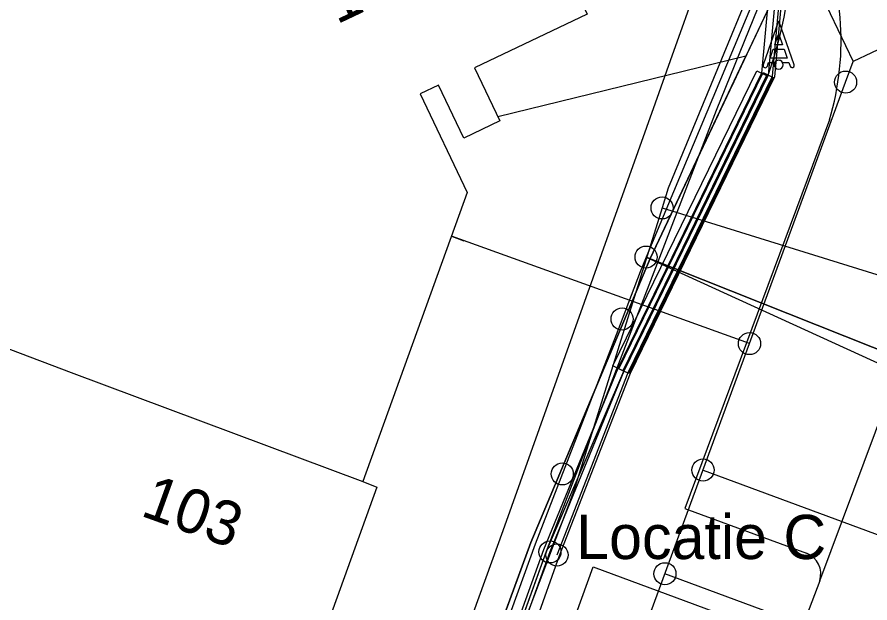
# Model space of a CAD drawing. Extents: x 192672 to 192910, y 446344 to 446512.
# Drawn here: x 192830.88 to 192850.15, y 446438.86 to 446452.12 of the extents above; entities that cross this region are included whole.
import ezdxf

# ---------------------------------------------------------------- set-up
doc = ezdxf.new("R2010")
doc.units = 0
for name, color, linetype in [('B-OI-KL-()_FIREHYDRANT_WATER-S', 7, 'Continuous'), ('B-OI-KL-()_MANTELBUIS_WATER-G', 7, 'Continuous'), ('B-OI-KL-()_PUNTVANLEVERING_WATER-S', 7, 'Continuous'), ('B-OI-KL-BUISLEIDING_OLIEGASCHEMICALIEN_GASLAGEDRUK-G', 7, 'Continuous'), ('B-OI-KL-DATA-G', 7, 'Continuous'), ('B-OI-KL-DATA_GTWP-S', 7, 'Continuous'), ('B-OI-KL-DATA_KABELBED-G', 7, 'Continuous'), ('B-OI-KL-DATA_MANTELBUIS-G', 7, 'Continuous'), ('B-OI-KL-DATA_MOF-S', 7, 'Continuous'), ('B-OI-KL-ET_LS-G', 7, 'Continuous'), ('B-OI-KL-ET_LS_MANTELBUIS-G', 7, 'Continuous'), ('B-OI-KL-ET_LS_MOF-S', 7, 'Continuous'), ('B-OI-KL-ET_MS-G', 7, 'Continuous'), ('B-OI-KL-ET_MS_MANTELBUIS-G', 7, 'Continuous'), ('B-OI-KL-GAS_LD_TSTUK-S', 7, 'Continuous'), ('B-OI-KL-WATER-G', 7, 'Continuous'), ('bovenleidingmast', 7, 'Continuous'), ('Default', 7, 'Continuous'), ('huisnummerreeks BGT', 7, 'Continuous'), ('kant open verharding', 7, 'Continuous'), ('kant verharding', 7, 'Continuous'), ('pand op maaiveld vlak', 7, 'Continuous'), ('TEKST', 7, 'Continuous')]:
    doc.layers.add(name, color=color, linetype=linetype)

# ---------------------------------------------------------------- blocks, each defined once
blk = doc.blocks.new('B-OI-KL-ET_LS_MOF-S')
at = {"layer": 'Default'}
blk.add_circle((0, 0), 0.25, dxfattribs=at)
blk = doc.blocks.new('B-OI-KL-GAS_LD_TSTUK-S')
at = {"layer": 'Default'}
blk.add_circle((0, 0), 0.25, dxfattribs=at)
blk = doc.blocks.new('B-OI-KL-()_FIREHYDRANT_WATER-S')
at = {"layer": 'Default'}
blk.add_circle((0, 0), 0.25, dxfattribs=at)
blk = doc.blocks.new('B-OI-KL-()_PUNTVANLEVERING_WATER-S')
at = {"layer": 'Default'}
blk.add_circle((0, 0), 0.25, dxfattribs=at)
blk = doc.blocks.new('B-OI-KL-DATA_GTWP-S')
at = {"layer": 'Default'}
blk.add_circle((0, 0), 0.25, dxfattribs=at)
blk = doc.blocks.new('B-OI-KL-DATA_MOF-S')
at = {"layer": 'Default'}
blk.add_circle((0, 0), 0.25, dxfattribs=at)

msp = doc.modelspace()

# ---------------------------------------------------------------- linework, layer by layer
at = {"layer": 'B-OI-KL-()_MANTELBUIS_WATER-G'}
msp.add_lwpolyline([(192840.69, 446447.157), (192840.972, 446447.055)], dxfattribs=at)
at = {"layer": 'B-OI-KL-BUISLEIDING_OLIEGASCHEMICALIEN_GASLAGEDRUK-G'}
for points in [[(192822.433, 446509.756), (192825.279, 446503.813), (192831.728, 446490.219), (192841.146, 446471.04), (192848.608, 446455.57), (192845.591, 446448.244), (192845.453, 446447.8)], [(192845.453, 446447.8), (192843.453, 446441.374), (192837.009, 446424.35), (192840.007, 446421.325), (192825.926, 446382.49)], [(192845.453, 446447.8), (192850.863, 446446.116), (192855.911, 446444.404), (192860.643, 446442.932)]]:
    msp.add_lwpolyline(points, dxfattribs=at)
at = {"layer": 'B-OI-KL-DATA-G'}
for points in [[(192821.742, 446509.756), (192825.984, 446501.22), (192835.895, 446480.007), (192842.472, 446466.378), (192848.635, 446454.503), (192848.764, 446454.232), (192845.185, 446446.654), (192842.489, 446440.231), (192836.203, 446423.068)], [(192821.742, 446509.756), (192825.984, 446501.22), (192835.895, 446480.007), (192842.472, 446466.378), (192848.635, 446454.503), (192848.764, 446454.232), (192845.185, 446446.654), (192842.489, 446440.231), (192836.203, 446423.068), (192839.811, 446421.866), (192851.515, 446418.004), (192854.977, 446417.712)], [(192821.742, 446509.756), (192825.984, 446501.22), (192835.895, 446480.007), (192842.472, 446466.378), (192848.635, 446454.503), (192848.764, 446454.232), (192845.185, 446446.654), (192842.489, 446440.231), (192836.203, 446423.068)], [(192821.742, 446509.756), (192825.984, 446501.22), (192835.895, 446480.007), (192842.472, 446466.378), (192848.635, 446454.503), (192848.764, 446454.232), (192845.185, 446446.654), (192842.489, 446440.231), (192836.203, 446423.068)], [(192821.742, 446509.756), (192825.984, 446501.22), (192835.895, 446480.007), (192842.472, 446466.378), (192848.635, 446454.503), (192848.764, 446454.232), (192845.185, 446446.654), (192842.489, 446440.231), (192836.203, 446423.068)], [(192821.742, 446509.756), (192825.984, 446501.22), (192835.895, 446480.007), (192842.472, 446466.378), (192848.635, 446454.503), (192848.764, 446454.232), (192845.185, 446446.654), (192842.489, 446440.231), (192836.203, 446423.068)], [(192821.742, 446509.756), (192825.984, 446501.22), (192835.895, 446480.007), (192842.472, 446466.378), (192848.635, 446454.503), (192848.764, 446454.232), (192845.185, 446446.654), (192842.489, 446440.231), (192836.203, 446423.068)], [(192821.742, 446509.756), (192825.984, 446501.22), (192835.895, 446480.007), (192842.472, 446466.378), (192848.635, 446454.503), (192848.764, 446454.232), (192845.185, 446446.654), (192842.489, 446440.231), (192836.203, 446423.068)], [(192821.742, 446509.756), (192825.984, 446501.22), (192835.895, 446480.007), (192842.472, 446466.378), (192848.635, 446454.503), (192848.764, 446454.232), (192845.185, 446446.654), (192842.489, 446440.231), (192836.203, 446423.068)], [(192675.743, 446430.36), (192720.2, 446413.771), (192739.906, 446406.53), (192752.421, 446411.058), (192770.152, 446404.44), (192773.577, 446403.064), (192825.629, 446383.71), (192826.856, 446388.539), (192834.171, 446407.983), (192839.017, 446421.742), (192838.042, 446426.7), (192842.865, 446440.095), (192846.683, 446450.008), (192848.26, 446453.903), (192848.365, 446454.374), (192848.254, 446454.945), (192844.011, 446462.681), (192860.643, 446470.952)], [(192854.977, 446417.712), (192851.515, 446418.004), (192839.811, 446421.866), (192836.203, 446423.068), (192842.489, 446440.231), (192845.185, 446446.654), (192847.347, 446451.231), (192841.744, 446449.857)], [(192854.977, 446417.712), (192851.515, 446418.004), (192839.811, 446421.866), (192836.203, 446423.068), (192842.489, 446440.231), (192845.185, 446446.654), (192847.347, 446451.231), (192841.744, 446449.857)], [(192854.977, 446417.712), (192851.515, 446418.004), (192839.811, 446421.866), (192836.203, 446423.068), (192842.489, 446440.231), (192845.185, 446446.654), (192847.347, 446451.231), (192841.744, 446449.857)], [(192854.977, 446417.712), (192851.515, 446418.004), (192839.811, 446421.866), (192836.203, 446423.068), (192842.489, 446440.231), (192845.185, 446446.654), (192847.347, 446451.231), (192841.744, 446449.857)], [(192854.977, 446417.712), (192851.515, 446418.004), (192839.811, 446421.866), (192836.203, 446423.068), (192842.489, 446440.231), (192845.185, 446446.654), (192847.347, 446451.231), (192841.744, 446449.857)], [(192854.977, 446417.712), (192851.515, 446418.004), (192839.811, 446421.866), (192836.203, 446423.068), (192842.489, 446440.231), (192845.185, 446446.654), (192847.347, 446451.231), (192841.744, 446449.857)], [(192854.977, 446417.712), (192851.515, 446418.004), (192839.811, 446421.866), (192836.203, 446423.068), (192842.489, 446440.231), (192845.185, 446446.654), (192847.347, 446451.231), (192841.744, 446449.857)], [(192854.977, 446417.712), (192851.515, 446418.004), (192839.811, 446421.866), (192836.203, 446423.068), (192842.489, 446440.231), (192845.185, 446446.654), (192847.347, 446451.231), (192841.744, 446449.857)]]:
    msp.add_lwpolyline(points, dxfattribs=at)
at = {"layer": 'B-OI-KL-DATA_KABELBED-G'}
for points in [[(192842.212, 446466.223), (192842.8, 446465.067), (192843.214, 446464.253), (192843.344, 446463.999), (192848.279, 446454.319), (192845.091, 446446.687)], [(192848.764, 446454.232), (192847.347, 446451.231)], [(192847.347, 446451.231), (192841.744, 446449.857)], [(192847.347, 446451.231), (192847.02, 446450.539)], [(192847.02, 446450.539), (192846.984, 446450.462)], [(192846.984, 446450.462), (192845.185, 446446.654), (192842.489, 446440.231), (192841.819, 446438.402)], [(192845.091, 446446.687), (192844.96, 446446.35), (192844.549, 446445.286)], [(192859.853, 446440.812), (192845.091, 446446.687)], [(192845.091, 446446.687), (192859.853, 446440.812), (192860.643, 446440.514)], [(192845.091, 446446.687), (192859.573, 446440.062), (192860.643, 446439.58)], [(192844.549, 446445.286), (192844.502, 446445.162), (192842.583, 446440.196), (192840.99, 446435.774)]]:
    msp.add_lwpolyline(points, dxfattribs=at)
at = {"layer": 'B-OI-KL-DATA_MANTELBUIS-G'}
msp.add_lwpolyline([(192859.853, 446440.812), (192845.091, 446446.687)], dxfattribs=at)
at = {"layer": 'B-OI-KL-ET_LS-G'}
for points in [[(192860.643, 446470.819), (192853.82, 446467.429), (192844.159, 446462.832), (192848.319, 446454.352), (192847.996, 446450.764), (192844.729, 446444.056), (192843.125, 446439.931), (192842.595, 446438.42)], [(192843.078, 446439.949), (192844.684, 446444.078), (192847.947, 446450.778), (192848.268, 446454.343), (192844.136, 446462.766), (192853.841, 446467.384), (192860.643, 446470.763)], [(192860.643, 446470.651), (192853.885, 446467.294), (192845.216, 446463.169), (192844.43, 446462.795), (192844.044, 446462.611), (192844.191, 446462.302), (192845.901, 446458.82), (192848.033, 446454.48), (192848.021, 446454.392), (192847.702, 446450.846), (192844.451, 446444.169), (192842.774, 446440.064), (192838.296, 446427.628), (192839.011, 446421.946), (192838.979, 446421.373), (192838.731, 446420.673), (192837.083, 446416.058), (192835.6, 446411.903), (192834.188, 446408.031), (192832.801, 446404.329), (192833.741, 446403.977)], [(192860.643, 446470.484), (192853.949, 446467.159), (192845.28, 446463.034), (192844.2, 446462.52), (192848.176, 446454.416), (192848.17, 446454.373), (192847.849, 446450.805), (192844.587, 446444.106), (192842.917, 446440.019)], [(192842.917, 446440.019), (192838.449, 446427.611), (192839.163, 446421.938), (192839.166, 446421.912), (192839.152, 446421.889), (192839.128, 446421.343), (192838.992, 446420.96), (192837.204, 446415.951), (192835.748, 446411.871), (192834.426, 446408.238), (192832.994, 446404.416), (192833.787, 446404.119)]]:
    msp.add_lwpolyline(points, dxfattribs=at)
at = {"layer": 'B-OI-KL-ET_LS_MANTELBUIS-G'}
msp.add_lwpolyline([(192847.996, 446450.764), (192844.729, 446444.056)], dxfattribs=at)
at = {"layer": 'B-OI-KL-ET_MS-G'}
msp.add_lwpolyline([(192806.764, 446390.772), (192825.096, 446383.91), (192826.671, 446388.028), (192834.794, 446409.643), (192839.188, 446421.141), (192838.367, 446427.603), (192842.844, 446440.037), (192844.587, 446444.106), (192847.849, 446450.805), (192847.991, 446451.236), (192848.111, 446451.673), (192848.209, 446452.116), (192848.285, 446452.564), (192848.339, 446453.014), (192848.37, 446453.467), (192848.378, 446453.921), (192848.364, 446454.374), (192844.011, 446462.68), (192853.853, 446467.362), (192860.643, 446470.735)], dxfattribs=at)
at = {"layer": 'B-OI-KL-ET_MS_MANTELBUIS-G'}
for points in [[(192844.563, 446444.114), (192844.339, 446444.224), (192847.59, 446450.901), (192847.814, 446450.791), (192844.563, 446444.114)], [(192844.699, 446444.051), (192844.475, 446444.161), (192847.737, 446450.86), (192847.961, 446450.75), (192844.699, 446444.051)], [(192844.587, 446444.106), (192847.849, 446450.805)]]:
    msp.add_lwpolyline(points, dxfattribs=at)
at = {"layer": 'B-OI-KL-WATER-G'}
for p, q in [((192821.752, 446509.756), (192849.771, 446451.113)), ((192860.643, 446456.219), (192849.771, 446451.113)), ((192846.378, 446441.87), (192860.643, 446436.574))]:
    msp.add_line(p, q, dxfattribs=at)
for points in [[(192849.599, 446450.644), (192849.771, 446451.113)], [(192826.018, 446386.448), (192827.039, 446389.193), (192849.599, 446450.644)], [(192847.428, 446444.73), (192840.69, 446447.157)], [(192858.635, 446434.656), (192845.516, 446439.523)]]:
    msp.add_lwpolyline(points, dxfattribs=at)
at = {"layer": 'bovenleidingmast'}
for p, q in [((192848.079, 446452.011), (192847.738, 446451.038)), ((192848.438, 446451.038), (192848.097, 446452.011))]:
    msp.add_line(p, q, dxfattribs=at)
for points in [[(192848.097, 446451.708), (192848.175, 446451.488), (192848.001, 446451.488), (192848.079, 446451.708)], [(192847.832, 446451.005), (192847.861, 446451.088), (192848.001, 446451.088)], [(192848.175, 446451.088), (192848.315, 446451.088), (192848.344, 446451.005)]]:
    msp.add_lwpolyline(points, dxfattribs=at)
msp.add_lwpolyline([(192848.21, 446451.388), (192848.28, 446451.188), (192847.896, 446451.188), (192847.966, 446451.388)], close=True, dxfattribs=at)
for centre, radius, start, end in [((192848.088, 446452.008), 0.01, 19.29, 160.71), ((192848.088, 446451.705), 0.01, 19.29, 160.71), ((192848.088, 446451.038), 0.1, 0, 180), ((192848.088, 446451.038), 0.1, 30, 150), ((192847.785, 446451.021), 0.05, 160.71, 340.71), ((192848.088, 446451.038), 0.1, 180, 0), ((192848.391, 446451.021), 0.05, 199.29, 19.29)]:
    msp.add_arc(centre, radius, start, end, dxfattribs=at)
at = {"layer": 'kant open verharding'}
for points in [[(192846.946, 446454.816), (192845.635, 446451.129), (192845.293, 446450.169), (192841.851, 446440.492), (192835.693, 446423.446), (192835.401, 446422.35)], [(192848.102, 446436.917), (192843.514, 446438.619), (192843.896, 446439.682), (192848.491, 446437.98)]]:
    msp.add_lwpolyline(points, dxfattribs=at)
at = {"layer": 'kant verharding'}
msp.add_line((192849.014, 446439.367), (192848.491, 446437.98), dxfattribs=at)
for points in [[(192849.014, 446439.367), (192852.558, 446448.85), (192852.92, 446450.686), (192852.89, 446452.743), (192852.529, 446454.425), (192852.02, 446455.701), (192852.016, 446455.709)], [(192849.233, 446449.789), (192845.968, 446441.003), (192848.719, 446439.99)]]:
    msp.add_lwpolyline(points, dxfattribs=at)
for centre, radius, start, end in [((192843.293, 446451.588), 6.206, 343.1487, 26.3848), ((192848.538, 446439.523), 0.501, 341.8227, 68.8539)]:
    msp.add_arc(centre, radius, start, end, dxfattribs=at)
at = {"layer": 'pand op maaiveld vlak'}
for points in [[(192836.54, 446469.53), (192836.973, 446468.62), (192837.036, 446468.487), (192838.86, 446464.658), (192838.011, 446464.254), (192843.76, 446452.181), (192841.215, 446450.969), (192841.788, 446449.766), (192840.974, 446449.379), (192840.403, 446450.578), (192839.983, 446450.377), (192841.046, 446448.145), (192838.693, 446441.612)], [(192829.348, 446445.115), (192832.102, 446444.08), (192838.693, 446441.612)], [(192838.693, 446441.612), (192839.008, 446441.484), (192836.921, 446435.689)]]:
    msp.add_lwpolyline(points, dxfattribs=at)

# ---------------------------------------------------------------- block references
at = {"layer": 'B-OI-KL-()_FIREHYDRANT_WATER-S'}
msp.add_blockref('B-OI-KL-()_FIREHYDRANT_WATER-S', (192849.599, 446450.644), dxfattribs=at)
at = {"layer": 'B-OI-KL-()_PUNTVANLEVERING_WATER-S'}
for p in [(192847.428, 446444.73), (192846.378, 446441.87), (192845.516, 446439.523)]:
    msp.add_blockref('B-OI-KL-()_PUNTVANLEVERING_WATER-S', p, dxfattribs=at)
at = {"layer": 'B-OI-KL-DATA_GTWP-S'}
for p in [(192845.091, 446446.687), (192845.091, 446446.687), (192845.091, 446446.687), (192845.091, 446446.687), (192844.549, 446445.286), (192844.549, 446445.286)]:
    msp.add_blockref('B-OI-KL-DATA_GTWP-S', p, dxfattribs=at)
at = {"layer": 'B-OI-KL-DATA_MOF-S'}
msp.add_blockref('B-OI-KL-DATA_MOF-S', (192843.196, 446441.782), dxfattribs=at)
at = {"layer": 'B-OI-KL-ET_LS_MOF-S'}
for p in [(192842.917, 446440.019), (192843.078, 446439.949)]:
    msp.add_blockref('B-OI-KL-ET_LS_MOF-S', p, dxfattribs=at)
at = {"layer": 'B-OI-KL-GAS_LD_TSTUK-S'}
msp.add_blockref('B-OI-KL-GAS_LD_TSTUK-S', (192845.453, 446447.8), dxfattribs=at)

# ---------------------------------------------------------------- texts
at = {"layer": 'huisnummerreeks BGT'}
for s, rotation, p in [('11-14', 25.4, (192838.098, 446451.943)), ('103', 340.2, (192833.638, 446440.847))]:
    msp.add_text(s, height=1, rotation=rotation, dxfattribs=at).set_placement(p)
at = {"layer": 'TEKST'}
msp.add_text('Locatie C', height=1, dxfattribs=at).set_placement((192843.511, 446439.857))

doc.saveas('drawing.dxf')
